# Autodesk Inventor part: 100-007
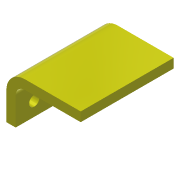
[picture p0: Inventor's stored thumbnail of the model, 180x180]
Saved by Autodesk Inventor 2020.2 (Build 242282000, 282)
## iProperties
Created: 2014-01
Part Number: 100-007
Material: Ogólny
Document SubType Name: Modeling
Designer: F.Stasiak
Density: 1 g/cm^3
Appearance: Gładki - żółty
Manager: www.cadconsulting.pl
Company: Fabian Stasiak CAD Consulting
Author: F.Stasiak
Subject: Zbiór ćwiczeń. Autodesk Inventor 2020. Kurs podstawowy
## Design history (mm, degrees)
sketch "Szkic1"
  geometry: L1 (0, 0)-(0, 20); L2 (0, 20)-(35, 20); L3 (35, 20)-(35, 25); L4 (35, 25)-(-5, 25); L5 (-5, 25)-(-5, 0); L6 (-5, 0)-(0, 0)
  constraints: 12 end point, 4 parallel, 1 perpendicular, 1 vertical
  dimensions: "d0" = 20 distance of L1.start L1.end; "d1" = 35 distance of L1.end L2.end; "d2" = 5 distance of L2.end L3.end; "d3" = 40 distance of L3.end L4.end
extrude "Wyciągnięcie proste1" new body sketch "Szkic1" distance "d4" = 50; taper "d5" = 0 deg
fillet "Zaokrąglenie1" dims "d6" = 5
fillet "Zaokrąglenie2" dims "d7" = 10
sketch "Szkic2"
  geometry: L1 (50, 0)-(0, 0) reference; L2 (50, 0)-(50, 15) reference; L3 (10, 7.5)-(40, 7.5); 3 further points
  constraints: 3 midpoint, 2 end point, 1 perpendicular, 1 point on line, 1 vertical alignment
  dimensions: "d8" = 30 distance of L3.start L3.end
hole "Otwór1" sketch "Szkic2" at (10, 7.5), (40, 7.5) diameter "d9" = 5.5; stored, may be unused: countersink angle "d13" = 90 deg, drill point angle "d15" = 118 deg; dims "d10" = 6, "d11" = 4, "d12" = 2, "d14" = 8
node "Bryła1"
